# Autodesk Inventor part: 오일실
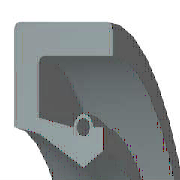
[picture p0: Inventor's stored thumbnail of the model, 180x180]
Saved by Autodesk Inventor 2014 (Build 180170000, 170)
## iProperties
IsCustomPart: 0
Created: 2009-02
Part Number: 오일실
Material: 고무
Description: 오일-실
Document SubType Name: Modeling
Standard: KS B 2804
Standards Organization: KS
Language: ko-KR
Size Designation: S - 17 30 8
Categories: <MemberInstance><Categories><Category DisplayName="샤프트 부품" InternalName="7f7aeb1f-a693-4053-b835-cee3144e0d98" Mnemonic="SHFT"><Category DisplayName="실링" Intern
Density: 0.93 g/cm^3
Appearance: 고무 - 검은색 - 버전 1.1
Author: pww
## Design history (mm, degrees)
revolve "본체" stored, may be unused: angle "d17" = 90 deg
revolve "스프링1" stored, may be unused: angle "d18" = 90 deg
body "Solid1"
sketch "스케치1"
  geometry: L1 (0, 15)-(8, 15); L2 (8, 15)-(8, 13.75); L3 (8, 13.75)-(1.75, 13.75); L4 (0, 15)-(0, 10.6); L5 (0, 10.6)-(1.75, 10.25); L6 (1.75, 10.25)-(4.9, 8.5); L7 (4.9, 8.5)-(0, 8.5); L8 (6.3, 9.375)-(6.3, 10.6); L9 (0, 0)-(9.586, 0) reference; L10 (4.9, 8.5)-(6.3, 9.375); L11 (0, 18)-(0, -3) reference; L12 (-1.917, 0)-(11.503, 0) reference; L13 (4.2, 10.6)-(1.75, 11.09); L14 (1.75, 11.09)-(1.75, 13.75); L15 (6.3, 10.6)-(5.6, 10.6); C1 r 0.455 at (4.9, 10.6); A1 r 0.7 centre (4.9, 10.6) between (5.6, 10.6) and (4.2, 10.6)
  constraints: 26 end point, 5 horizontal alignment, 4 perpendicular, 2 centre point, 2 collinear, 2 horizontal, 2 parallel, 2 point on circle, 2 point on line, 2 vertical alignment, 1 coincident
  dimensions: "d0" = 30 diameter of L1 L9 (= SD2); "d1" = 18.75 diameter of L8.start L9 (= ABDM); "d2" = 1.25 distance of L1.end L2.end (computed from SD); "d3" = 0.91 diameter of C1 (= SPDI); "d4" = 1.4 diameter of A1 (= SPDA); "d5" = 17 diameter of L6.end L9 (= NND); "d6" = 20.5 diameter of L5.end L9 (= TKDM); "d7" = 21.2 diameter of L4.end L9 (= HLDM); "d8" = 4.9 distance from line of C1.centre L4 (= SPDST); "d9" = 6.3 distance between parallel lines of L8 L4 (= SDI); "d10" = 8 distance between parallel lines of L2 L4 (= SWDT); "d12" = 1.75 distance between parallel lines of L14 L4 (= SD)
fillet "모깎기1" dims "d11" = 0.3 (= RR)
other parameters: "SD2" = 30 [user parameter; used in 1 equation term], "SWDT" = 8 [user parameter; used in 1 equation term], "RR" = 0.3 [user parameter; used in 1 equation term], "SD" = 1.75 [user parameter; used in 2 equation terms], "NND" = 17 [user parameter; used in 1 equation term], "SPDA" = 1.4 [user parameter; used in 1 equation term], "SPDI" = 0.91 [user parameter; used in 1 equation term], "TKDM" = 20.5 [user parameter; used in 1 equation term], "HLDM" = 21.2 [user parameter; used in 1 equation term], "ABDM" = 18.75 [user parameter; used in 1 equation term], "SDI" = 6.3 [user parameter; used in 1 equation term], "SPDST" = 4.9 [user parameter; used in 1 equation term], "d13" = 0, "d14" = 0, "d15" = 0, "LAB" = 0.35 [user parameter]
